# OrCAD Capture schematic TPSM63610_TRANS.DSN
size Custom; title: TPSM63610: 8-A Automotive Buck Power Module; rev: 1.0; note: Datasheet: SLVSGU1    EVM: SLVUCF1; note: Synchronous Step Down Converter
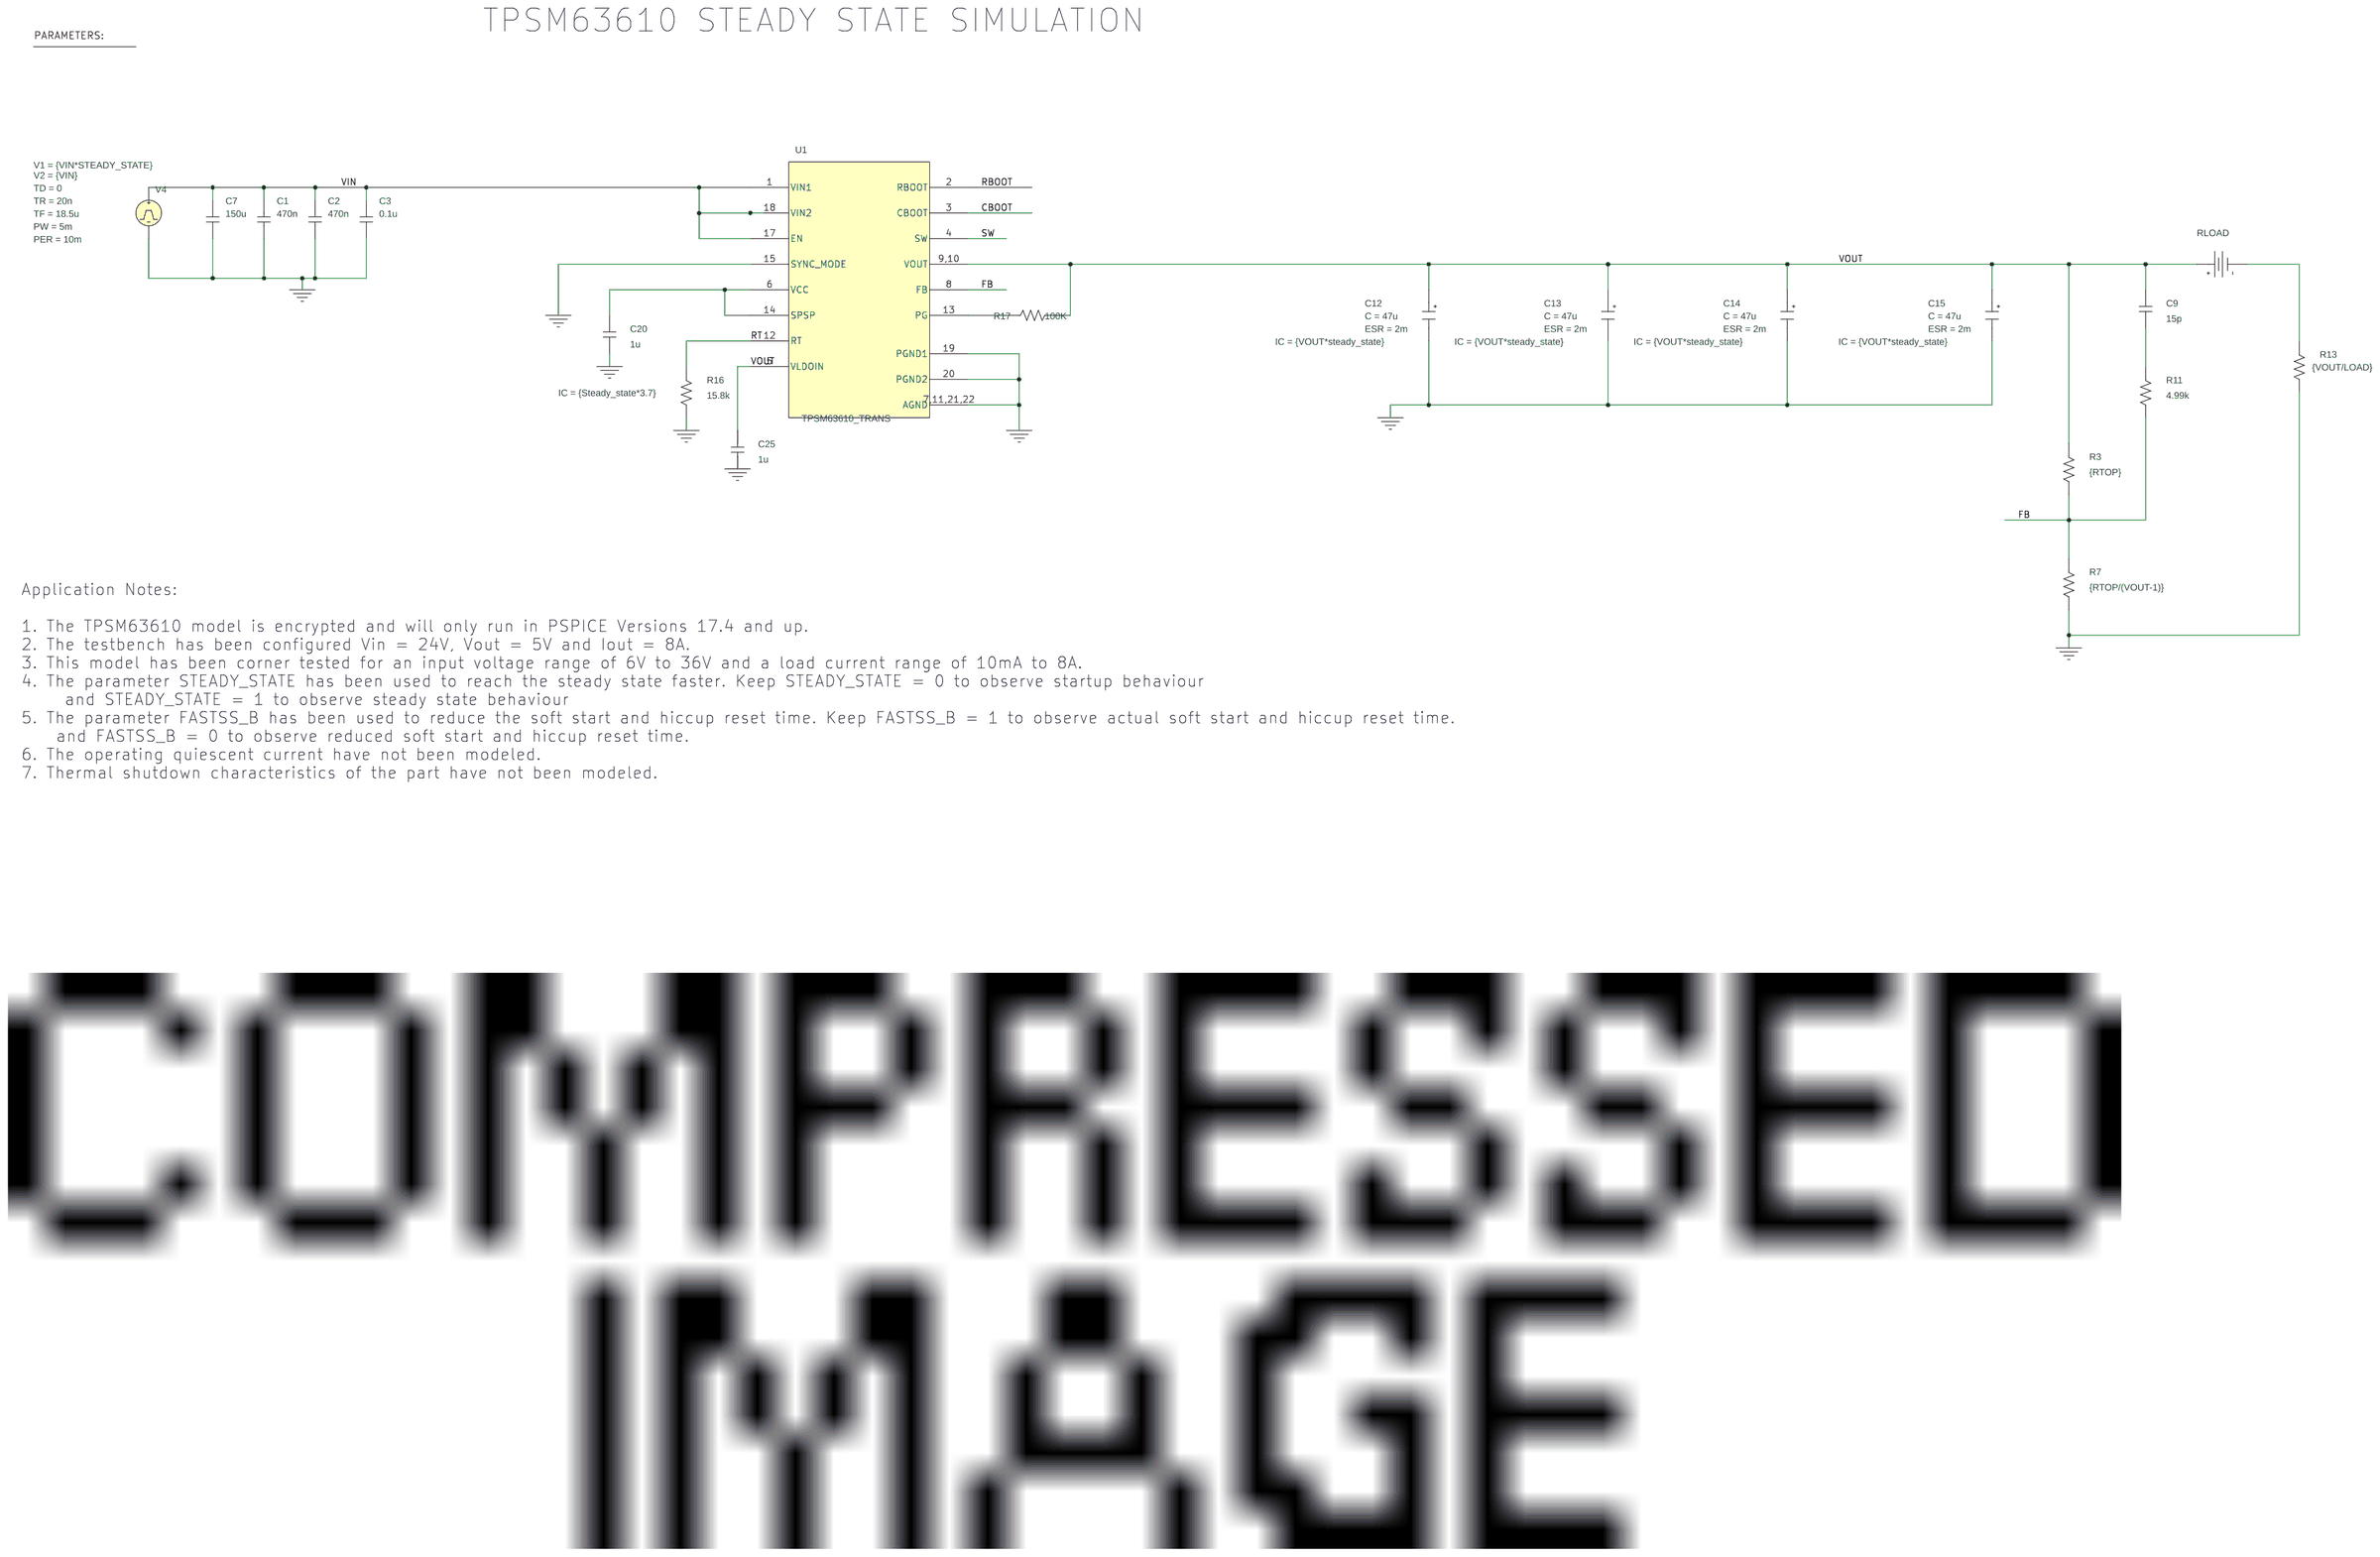
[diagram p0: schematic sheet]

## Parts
1  PARAM
C1  470n  [RAD/CK05]
C2  470n  [RAD/CK05]
C3  0.1u  [RAD/CK05]
C7  150u  [RAD/CK05]
C9  15p  [RAD/CK05]
C12  CESR
C13  CESR
C14  CESR
C15  CESR
C20  1u  [RAD/CK05]
C25  1u  [RAD/CK05]
R3  {RTOP}  [AX/RC05]
R7  {RTOP/(VOUT-1)}  [AX/RC05]
R11  4.99k  [AX/RC05]
R13  {VOUT/LOAD}  [AX/RC05]
R16  15.8k  [AX/RC05]
R17  100K  [AX/RC05]
RLOAD  VDC
U1  TPSM63610_TRANS
V4  VPULSE

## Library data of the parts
1 = PARAM: LOAD: 8; RDSON_HS: 21m; RDSON_LS: 13m; RTOP: 100k; VIN: 24; VOUT: 5
C1-C3 C7 C9 C25 = C
C12-C15 = CESR_0: C: 47u; ESR: 2m; IC: {VOUT*steady_state}; PSpiceTemplate: X^@REFDES %IN %OUT @MODEL PARAMS:  ?C|C=@C||C=100u|  ?ESR|ESR=@ESR||ESR=0.01| ?X|X=@X||X=2|  ?IC|IC=@IC||IC=2|; X: 1
C20 = C: IC: {Steady_state*3.7}
R3 R7 R11 R13 R16 R17 = r
RLOAD = VDC
U1 = TPSM63610_TRANS_1
V4 = VPULSE: PER: 10m; PW: 5m; TD: 0; TF: 18.5u; TR: 20n; V1: {VIN*STEADY_STATE}; V2: {VIN}

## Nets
VIN: C1.1 C2.1 C3.1 C7.1 U1.1(VIN1) U1.17(EN) U1.18(VIN2) V4.1(+)
0: C1.2 C2.2 C3.2 C7.2 C12.2(OUT) C13.2(OUT) C14.2(OUT) C15.2(OUT) C20.2 C25.2 R7.2 R13.2 R16.2 U1.7,11,21,22(AGND) U1.15(SYNC_MODE) U1.19(PGND1) U1.20(PGND2) V4.2(-)
CBOOT: U1.3(CBOOT)
FB: R3.2 R7.1 R11.2 U1.8(FB)
RBOOT: U1.2(RBOOT)
RT: R16.1 U1.12(RT)
SW: U1.4(SW)
VOUT: C9.1 C12.1(IN) C13.1(IN) C14.1(IN) C15.1(IN) C25.1 R3.1 R17.2 RLOAD.0(+) U1.5(VLDOIN) U1.9,10(VOUT)
N78707: R13.1 RLOAD.1(-)
N78753: C20.1 U1.6(VCC) U1.14(SPSP)
N78969: R17.1 U1.13(PG)
N78997: C9.2 R11.1

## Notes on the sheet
- TPSM63610 STEADY STATE SIMULATION
- Application Notes:
  1. The TPSM63610 model is encrypted and will only run in PSPICE Versions 17.4 and up.
  2. The testbench has been configured Vin = 24V, Vout = 5V and Iout = 8A.
  3. This model has been corner tested for an input voltage range of 6V to 36V and a load current range of 10mA to 8A.
  4. The parameter STEADY_STATE has been used to reach the steady state faster. Keep STEADY_STATE = 0 to observe startup behaviour
       and STEADY_STATE = 1 to observe steady state behaviour
  5. The parameter FASTSS_B has been used to reduce the soft start and hiccup reset time. Keep FASTSS_B = 1 to observe actual soft start and hiccup reset time.
      and FASTSS_B = 0 to observe reduced soft start and hiccup reset time.
  6. The operating quiescent current have not been modeled.
  7. Thermal shutdown characteristics of the part have not been modeled.
